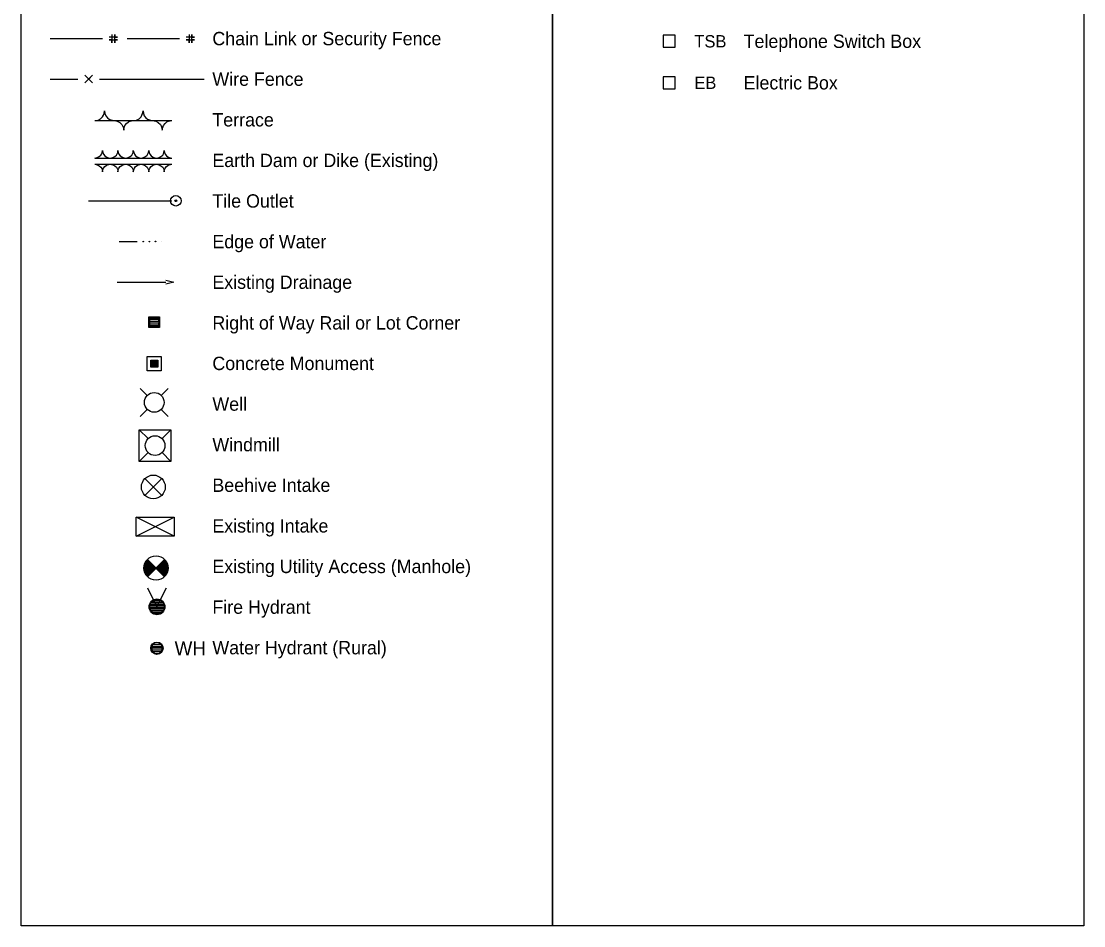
# Model space of a CAD drawing. Extents: x 6082259 to 6083454, y 5964102 to 5966092.
# Drawn here: x 6082259 to 6083454, y 5964102 to 5965119 of the extents above; entities that cross this region are included whole.
import ezdxf

# ---------------------------------------------------------------- set-up
doc = ezdxf.new("R2010")
doc.units = 0
for name, color, linetype in [('Default', 7, 'Continuous'), ('SurControl', 7, 'Continuous'), ('Text', 7, 'Continuous')]:
    doc.layers.add(name, color=color, linetype=linetype)

msp = doc.modelspace()

# ---------------------------------------------------------------- linework, layer by layer
at = {"layer": 'Default'}
for points in [[(6082259, 5966092.2), (6082856.5, 5966092.2), (6082856.5, 5964102.2), (6082259, 5964102.2)], [(6082856.5, 5966092.2), (6083454, 5966092.2), (6083454, 5964102.2), (6082856.5, 5964102.2)]]:
    msp.add_lwpolyline(points, close=True, dxfattribs=at)
at = {"layer": 'Text'}
for p, q in [((6082334.7, 5964916.8), (6082428.3, 5964916.8)), ((6082369, 5964871.1), (6082389.5, 5964871.1)), ((6082410, 5964871.1), (6082410, 5964871.1)), ((6082417, 5964871.3), (6082417, 5964871.3)), ((6082367, 5964825.4), (6082421.8, 5964825.4)), ((6082421.5, 5964827.8), (6082430.6, 5964825.5)), ((6082430.6, 5964825.5), (6082421.5, 5964823.2)), ((6082392.8, 5964706.1), (6082400.7, 5964698.3)), ((6082416.5, 5964698.3), (6082424.4, 5964706.1)), ((6082392.8, 5964674.6), (6082400.7, 5964682.5)), ((6082416.5, 5964682.5), (6082424.4, 5964674.6)), ((6082391.8, 5964659.7), (6082401.7, 5964649.7)), ((6082417.5, 5964649.7), (6082427.4, 5964659.7)), ((6082391.8, 5964624), (6082401.7, 5964634)), ((6082417.5, 5964634), (6082427.4, 5964624)), ((6082398.2, 5964585.8), (6082417.1, 5964604.7)), ((6082398.2, 5964604.7), (6082417.1, 5964585.8)), ((6082400.9, 5964494.5), (6082420.3, 5964513.9)), ((6082400.9, 5964513.9), (6082420.3, 5964494.5)), ((6082401, 5964482), (6082411.7, 5964460.6)), ((6082411.7, 5964460.6), (6082422.4, 5964482))]:
    msp.add_line(p, q, dxfattribs=at)
for points in [[(6082291.6, 5965099.3), (6082350.5, 5965099.3)], [(6082361.1, 5965104), (6082361.1, 5965094.6), (6082361.1, 5965097.8), (6082358, 5965097.8), (6082367.3, 5965097.8), (6082364.2, 5965097.8), (6082364.2, 5965094.6), (6082364.2, 5965104), (6082364.2, 5965100.9), (6082367.3, 5965100.9), (6082358, 5965100.9)], [(6082378.3, 5965099.3), (6082437.2, 5965099.3)], [(6082447.8, 5965104), (6082447.8, 5965094.6), (6082447.8, 5965097.8), (6082444.7, 5965097.8), (6082454, 5965097.8), (6082450.9, 5965097.8), (6082450.9, 5965094.6), (6082450.9, 5965104), (6082450.9, 5965100.9), (6082454, 5965100.9), (6082444.7, 5965100.9)], [(6082987.8, 5965089.5), (6082987.8, 5965089.5), (6082994.6, 5965089.5), (6082994.6, 5965103.1), (6082981, 5965103.1), (6082981, 5965089.5), (6082987.8, 5965089.5)], [(6082330.6, 5965049.4), (6082339.3, 5965058), (6082334.9, 5965053.7), (6082339.3, 5965049.4), (6082330.6, 5965058)], [(6082291.6, 5965053.7), (6082322.8, 5965053.7)], [(6082347.1, 5965053.7), (6082464.9, 5965053.7)], [(6082987.8, 5965042.8), (6082987.8, 5965042.8), (6082994.6, 5965042.8), (6082994.6, 5965056.4), (6082981, 5965056.4), (6082981, 5965042.8), (6082987.8, 5965042.8)], [(6082341.8, 5965007.1), (6082345.4, 5965007.7), (6082348.1, 5965009.2), (6082350.5, 5965011.5), (6082351.5, 5965013.1), (6082352.2, 5965015.2), (6082352.6, 5965018), (6082353, 5965014.9), (6082354, 5965012.6), (6082355.9, 5965010.2), (6082357.9, 5965008.7), (6082359.8, 5965007.8), (6082363.4, 5965007.1)], [(6082385.1, 5965007.1), (6082388.7, 5965007.7), (6082391.5, 5965009.2), (6082393.8, 5965011.5), (6082394.8, 5965013.1), (6082395.6, 5965015.2), (6082396, 5965018), (6082396.4, 5965014.9), (6082397.4, 5965012.6), (6082399.2, 5965010.2), (6082401.2, 5965008.7), (6082403.2, 5965007.8), (6082406.8, 5965007.1)], [(6082341.8, 5965007.1), (6082428.5, 5965007.1)], [(6082363.4, 5965007.1), (6082367, 5965006.5), (6082369.8, 5965005.1), (6082372.1, 5965002.8), (6082373.1, 5965001.2), (6082373.9, 5964999.1), (6082374.3, 5964996.3), (6082374.7, 5964999.3), (6082375.7, 5965001.7), (6082377.5, 5965004), (6082379.6, 5965005.6), (6082381.5, 5965006.5), (6082385.1, 5965007.1)], [(6082406.8, 5965007.1), (6082410.4, 5965006.5), (6082413.1, 5965005.1), (6082415.5, 5965002.8), (6082416.5, 5965001.2), (6082417.3, 5964999.1), (6082417.6, 5964996.3), (6082418.1, 5964999.3), (6082419, 5965001.7), (6082420.9, 5965004), (6082422.9, 5965005.6), (6082424.8, 5965006.5), (6082428.5, 5965007.1)], [(6082341.8, 5964965), (6082344.6, 5964965.5), (6082346.8, 5964966.6), (6082348.7, 5964968.4), (6082349.5, 5964969.7), (6082350.2, 5964971.4), (6082350.4, 5964973.6), (6082350.8, 5964971.2), (6082351.6, 5964969.3), (6082353, 5964967.4), (6082354.7, 5964966.2), (6082356.2, 5964965.5), (6082359.1, 5964965)], [(6082341.8, 5964965), (6082428.5, 5964965)], [(6082359.1, 5964965), (6082362, 5964965.5), (6082364.2, 5964966.6), (6082366.1, 5964968.4), (6082366.9, 5964969.7), (6082367.5, 5964971.4), (6082367.8, 5964973.6), (6082368.1, 5964971.2), (6082368.9, 5964969.3), (6082370.4, 5964967.4), (6082372, 5964966.2), (6082373.5, 5964965.5), (6082376.5, 5964965)], [(6082376.5, 5964965), (6082379.3, 5964965.5), (6082381.5, 5964966.6), (6082383.4, 5964968.4), (6082384.2, 5964969.7), (6082384.8, 5964971.4), (6082385.1, 5964973.6), (6082385.5, 5964971.2), (6082386.3, 5964969.3), (6082387.7, 5964967.4), (6082389.3, 5964966.2), (6082390.9, 5964965.5), (6082393.8, 5964965)], [(6082393.8, 5964965), (6082396.6, 5964965.5), (6082398.9, 5964966.6), (6082400.7, 5964968.4), (6082401.5, 5964969.7), (6082402.2, 5964971.4), (6082402.5, 5964973.6), (6082402.8, 5964971.2), (6082403.6, 5964969.3), (6082405.1, 5964967.4), (6082406.7, 5964966.2), (6082408.2, 5964965.5), (6082411.1, 5964965)], [(6082411.1, 5964965), (6082414, 5964965.5), (6082416.2, 5964966.6), (6082418.1, 5964968.4), (6082418.9, 5964969.7), (6082419.5, 5964971.4), (6082419.8, 5964973.6), (6082420.1, 5964971.2), (6082420.9, 5964969.3), (6082422.4, 5964967.4), (6082424, 5964966.2), (6082425.5, 5964965.5), (6082428.5, 5964965)], [(6082341.8, 5964958), (6082359.1, 5964958)], [(6082341.8, 5964958), (6082344.6, 5964957.5), (6082346.8, 5964956.4), (6082348.7, 5964954.6), (6082349.5, 5964953.3), (6082350.2, 5964951.6), (6082350.4, 5964949.4), (6082350.8, 5964951.8), (6082351.6, 5964953.7), (6082353, 5964955.6), (6082354.7, 5964956.8), (6082356.2, 5964957.5), (6082359.1, 5964958)], [(6082359.1, 5964958), (6082376.4, 5964958)], [(6082359.1, 5964958), (6082362, 5964957.5), (6082364.2, 5964956.4), (6082366.1, 5964954.6), (6082366.9, 5964953.3), (6082367.5, 5964951.6), (6082367.8, 5964949.4), (6082368.1, 5964951.8), (6082368.9, 5964953.7), (6082370.4, 5964955.6), (6082372, 5964956.8), (6082373.5, 5964957.5), (6082376.4, 5964958)], [(6082376.5, 5964958), (6082393.8, 5964958)], [(6082376.5, 5964958), (6082379.3, 5964957.5), (6082381.5, 5964956.4), (6082383.4, 5964954.6), (6082384.2, 5964953.3), (6082384.8, 5964951.6), (6082385.1, 5964949.4), (6082385.5, 5964951.8), (6082386.3, 5964953.7), (6082387.7, 5964955.6), (6082389.3, 5964956.8), (6082390.9, 5964957.5), (6082393.8, 5964958)], [(6082393.8, 5964958), (6082411.1, 5964958)], [(6082393.8, 5964958), (6082396.6, 5964957.5), (6082398.9, 5964956.4), (6082400.7, 5964954.6), (6082401.5, 5964953.3), (6082402.2, 5964951.6), (6082402.5, 5964949.4), (6082402.8, 5964951.8), (6082403.6, 5964953.7), (6082405.1, 5964955.6), (6082406.7, 5964956.8), (6082408.2, 5964957.5), (6082411.1, 5964958)], [(6082411.1, 5964958), (6082428.5, 5964958)], [(6082411.1, 5964958), (6082414, 5964957.5), (6082416.2, 5964956.4), (6082418.1, 5964954.6), (6082418.9, 5964953.3), (6082419.5, 5964951.6), (6082419.8, 5964949.4), (6082420.1, 5964951.8), (6082420.9, 5964953.7), (6082422.4, 5964955.6), (6082424, 5964956.8), (6082425.5, 5964957.5), (6082428.5, 5964958)], [(6082403.7, 5964775.6), (6082403.7, 5964785.5), (6082413.6, 5964785.5), (6082413.6, 5964775.6), (6082403.7, 5964775.6), (6082403.7, 5964777.5), (6082413.6, 5964777.5), (6082413.6, 5964779.5), (6082403.7, 5964779.5), (6082403.7, 5964781.5), (6082413.6, 5964781.5), (6082413.6, 5964783.5), (6082403.7, 5964783.5)], [(6082400.7, 5964726), (6082400.7, 5964741.9), (6082416.5, 5964741.9), (6082416.5, 5964726), (6082400.7, 5964726)], [(6082404.6, 5964730), (6082404.6, 5964737.9), (6082412.6, 5964737.9), (6082412.6, 5964730), (6082404.6, 5964730), (6082405.6, 5964731), (6082405.6, 5964736.9), (6082411.6, 5964736.9), (6082411.6, 5964731), (6082406.6, 5964731), (6082406.6, 5964735.9), (6082410.6, 5964735.9), (6082410.6, 5964732), (6082407.6, 5964732), (6082407.6, 5964734.9), (6082409.6, 5964734.9), (6082409.6, 5964733), (6082408.6, 5964733), (6082408.6, 5964734)], [(6082388.2, 5964540), (6082431, 5964561.4), (6082431, 5964540), (6082388.2, 5964561.4)], [(6082400.7, 5964495.3), (6082401.2, 5964495.3), (6082402.2, 5964496.3), (6082400.2, 5964496.3), (6082399.2, 5964497.3), (6082403.2, 5964497.3), (6082404.2, 5964498.3), (6082398.7, 5964498.3), (6082398.2, 5964499.3), (6082405.1, 5964499.3), (6082406.1, 5964500.3), (6082398.2, 5964500.3), (6082397.7, 5964501.2), (6082407.1, 5964501.2), (6082408.1, 5964502.2), (6082397.7, 5964502.2), (6082397.2, 5964503.2), (6082409.1, 5964503.2), (6082410.1, 5964504.2), (6082397.2, 5964504.2), (6082397.2, 5964505.2), (6082409.1, 5964505.2), (6082408.1, 5964506.2), (6082397.7, 5964506.2), (6082397.7, 5964507.2), (6082407.1, 5964507.2), (6082406.1, 5964508.2), (6082397.7, 5964508.2), (6082398.2, 5964509.2), (6082405.1, 5964509.2), (6082404.2, 5964510.2), (6082398.7, 5964510.2), (6082399.2, 5964511.1), (6082403.2, 5964511.1), (6082402.2, 5964512.1), (6082399.7, 5964512.1), (6082400.7, 5964513.1), (6082401.2, 5964513.1), (6082410.1, 5964504.2), (6082401.2, 5964495.3), (6082400.7, 5964495.3), (6082399.2, 5964497.3), (6082397.7, 5964501.2), (6082397.2, 5964505.2), (6082398.2, 5964509.2), (6082400.7, 5964513.1)], [(6082420.5, 5964495.3), (6082420, 5964495.3), (6082419, 5964496.3), (6082421, 5964496.3), (6082422, 5964497.3), (6082418, 5964497.3), (6082417, 5964498.3), (6082422.5, 5964498.3), (6082423, 5964499.3), (6082416, 5964499.3), (6082415, 5964500.3), (6082423, 5964500.3), (6082423.5, 5964501.2), (6082414.1, 5964501.2), (6082413.1, 5964502.2), (6082423.5, 5964502.2), (6082424, 5964503.2), (6082412.1, 5964503.2), (6082411.1, 5964504.2), (6082424, 5964504.2), (6082424, 5964505.2), (6082412.1, 5964505.2), (6082413.1, 5964506.2), (6082423.5, 5964506.2), (6082423.5, 5964507.2), (6082414.1, 5964507.2), (6082415, 5964508.2), (6082423.5, 5964508.2), (6082423, 5964509.2), (6082416, 5964509.2), (6082417, 5964510.2), (6082422.5, 5964510.2), (6082422, 5964511.1), (6082418, 5964511.1), (6082419, 5964512.1), (6082421.5, 5964512.1), (6082420.5, 5964513.1), (6082420, 5964513.1), (6082411.1, 5964504.2), (6082420, 5964495.3), (6082420.5, 5964495.3), (6082422, 5964497.3), (6082423.5, 5964501.2), (6082424, 5964505.2), (6082423, 5964509.2), (6082420.5, 5964513.1)], [(6082413.2, 5964469), (6082410.2, 5964469), (6082406.3, 5964467.1), (6082404.3, 5964464.6), (6082403.3, 5964461.1), (6082403.8, 5964457.7), (6082406.3, 5964454.2), (6082408.7, 5964452.7), (6082411.7, 5964452.2), (6082414.7, 5964452.7), (6082417.7, 5964454.7), (6082419.6, 5964457.7), (6082420.1, 5964460.6), (6082419.6, 5964463.6), (6082418.2, 5964466.1), (6082415.7, 5964468.1), (6082413.2, 5964469), (6082416.7, 5964467.6), (6082407.3, 5964467.6), (6082405.3, 5964466.1), (6082418.2, 5964466.1), (6082419.1, 5964464.6), (6082404.3, 5964464.6), (6082403.8, 5964463.1), (6082419.6, 5964463.1), (6082420.1, 5964461.6), (6082403.3, 5964461.6), (6082403.3, 5964460.1), (6082420.1, 5964460.1), (6082419.6, 5964458.6), (6082403.8, 5964458.6), (6082404.3, 5964457.2), (6082419.1, 5964457.2), (6082418.2, 5964455.7), (6082405.3, 5964455.7), (6082406.3, 5964454.2), (6082417.2, 5964454.2), (6082414.7, 5964452.7), (6082408.7, 5964452.7)], [(6082413.7, 5964420), (6082409.7, 5964420), (6082406.8, 5964418), (6082405.8, 5964416), (6082405.8, 5964412.1), (6082406.8, 5964410.1), (6082409.7, 5964408.1), (6082413.7, 5964408.1), (6082416.7, 5964410.1), (6082417.7, 5964412.1), (6082417.7, 5964416), (6082416.7, 5964418), (6082413.7, 5964420), (6082416.7, 5964418), (6082406.8, 5964418), (6082405.8, 5964416), (6082417.7, 5964416), (6082417.7, 5964414.1), (6082405.8, 5964414.1), (6082405.8, 5964412.1), (6082417.7, 5964412.1), (6082416.7, 5964410.1), (6082406.8, 5964410.1)]]:
    msp.add_lwpolyline(points, dxfattribs=at)
for points in [[(6082402.7, 5964774.6), (6082402.7, 5964786.5), (6082414.6, 5964786.5), (6082414.6, 5964774.6)], [(6082391.8, 5964624), (6082391.8, 5964659.7), (6082427.4, 5964659.7), (6082427.4, 5964624)], [(6082388.2, 5964540), (6082388.2, 5964561.4), (6082431, 5964561.4), (6082431, 5964540)]]:
    msp.add_lwpolyline(points, close=True, dxfattribs=at)
for centre, radius in [((6082432.9, 5964917), 5.94), ((6082432.9, 5964917), 0.991), ((6082396.3, 5964871.1), 0.342), ((6082403.2, 5964871.1), 0.342), ((6082410, 5964871.3), 0.342), ((6082408.6, 5964690.4), 11.1), ((6082409.6, 5964641.8), 11.1), ((6082407.6, 5964595.3), 13.4), ((6082410.6, 5964504.2), 13.7), ((6082411.7, 5964460.6), 8.92), ((6082411.7, 5964414.1), 6.93)]:
    msp.add_circle(centre, radius, dxfattribs=at)

# ---------------------------------------------------------------- texts
at = {"layer": 'SurControl'}
for s, p in [('Chain Link or Security Fence', (6082474, 5965091.8)), ('Telephone Switch Box', (6083071.5, 5965088.8)), ('Wire Fence', (6082474, 5965046.2)), ('Electric Box', (6083071.5, 5965042.1)), ('Terrace', (6082474, 5965000.5)), ('Earth Dam or Dike (Existing)', (6082474, 5964954.9)), ('Tile Outlet', (6082474, 5964909.3)), ('Edge of Water', (6082474, 5964863.6)), ('Existing Drainage', (6082474, 5964818)), ('Right of Way Rail or Lot Corner', (6082474, 5964772.3)), ('Concrete Monument', (6082474, 5964726.7)), ('Windmill', (6082474, 5964635.4)), ('Beehive Intake', (6082474, 5964589.8)), ('Existing Intake', (6082474, 5964544.1)), ('Existing Utility Access (Manhole)', (6082474, 5964498.5)), ('Fire Hydrant', (6082474, 5964452.8)), ('Water Hydrant (Rural)', (6082474, 5964407.2))]:
    msp.add_text(s, height=15, dxfattribs=at).set_placement(p)
at = {"layer": 'Text'}
for s, height, p in [('TSB', 13.87, (6083016.1, 5965089.3)), ('EB', 13.87, (6083016.1, 5965042.7)), ('Well', 15, (6082474, 5964681)), ('WH', 15.85, (6082431.5, 5964406.1))]:
    msp.add_text(s, height=height, dxfattribs=at).set_placement(p)

doc.saveas('drawing.dxf')
